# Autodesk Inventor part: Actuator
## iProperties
Created: 2009-03
Part Number: Actuator
Document SubType Name: Modeling
Designer: tangg
Density: 7.84 g/cm^3
Material: Steel, High Strength Low Alloy
Mass: 5.99349 g
Surface Area: 9.85126 cm^2
Volume: 0.764475 cm^3
Author: tangg
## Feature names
1. Extrusion1
2. Split1
3. Split2
4. Extrusion2
5. Split3
6. Split4
7. Split5
8. Chamfer1
9. Chamfer2
10. Revolution1
